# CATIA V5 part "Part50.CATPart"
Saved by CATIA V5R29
Part number: Connect
Revision: ANY
Definition: UNKNOWN
Nomenclature: Connect
Source: Unknown
Bounding box of the stored display mesh (mm): x 18.54 to 26.04, y -7.5 to 7.5, z -7.5 to 7.5
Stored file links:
  C:\Users\Administrator\Desktop\프로젝트\Gripper\Part50.CATPart
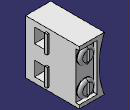
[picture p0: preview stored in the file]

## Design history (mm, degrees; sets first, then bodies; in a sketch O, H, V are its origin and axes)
Body1 "Cut-Extrude3" (main body)
  Solid1: solid without history
Body2 "Boss-Extrude2[1]"
  Solid2: solid without history
Body3 "Boss-Extrude2[2]"
  Solid3: solid without history
Body4 "Cut-Extrude4"
  Solid4: solid without history
Body5 "Mirror1"
  Solid5: solid without history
